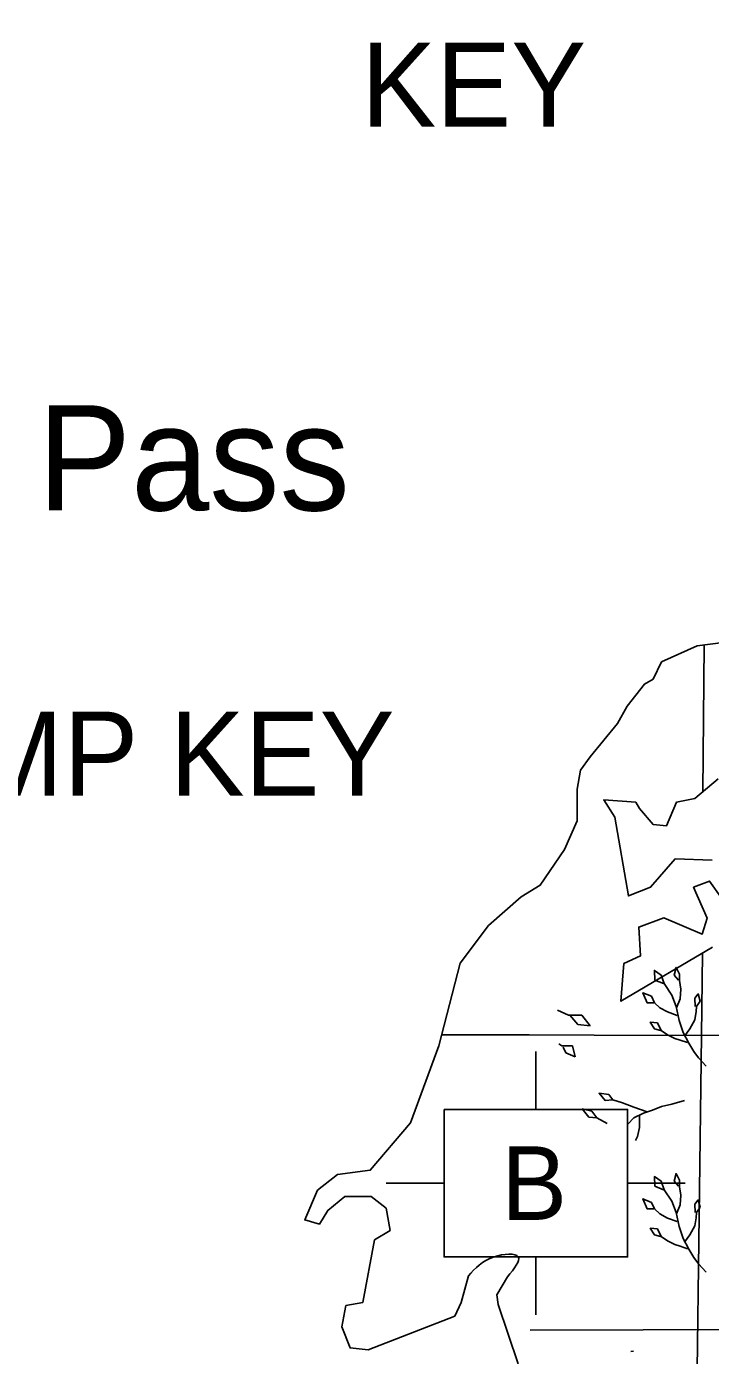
# Model space of a CAD drawing. Extents: x 380424 to 701066, y 1117407 to 1412949.
# Drawn here: x 485366 to 488619, y 1219155 to 1225474 of the extents above; entities that cross this region are included whole.
import ezdxf

# ---------------------------------------------------------------- set-up
doc = ezdxf.new("R2010")
doc.units = 0
for name, color, linetype in [('Bayou and Harbor etc Text', 7, 'Continuous'), ('Cities Incorporated Area', 7, 'Continuous'), ('Culture', 7, 'Continuous'), ('Islands Text Coastal (Keys etc)', 7, 'Continuous'), ('Local Roads Paved', 7, 'Continuous'), ('Mangroves', 7, 'Continuous'), ('Section Lines', 7, 'Continuous')]:
    doc.layers.add(name, color=color, linetype=linetype)

msp = doc.modelspace()

# ---------------------------------------------------------------- linework, layer by layer
at = {"layer": 'Cities Incorporated Area'}
for points in [[(488913.9, 1222575.8), (488557, 1222529), (488387.3, 1222452.9), (488346.3, 1222370.9), (488305.4, 1222347.5), (488223.4, 1222242.1), (488176.6, 1222160.1), (488047.9, 1222002), (488001.1, 1221938.9), (487986, 1221848.3), (487986, 1221697.5), (487925.7, 1221561.7), (487810.1, 1221390.7), (487719.6, 1221335.4), (487563.8, 1221199.6), (487428.1, 1221020), (487327.6, 1220628), (487191.9, 1220261.5), (487000.9, 1220036), (486845.1, 1220015.9), (486749.6, 1219940.4), (486689.3, 1219799.6), (486759.7, 1219779.5), (486799.9, 1219844.9), (486880.3, 1219910.3), (487006, 1219910.3), (487076.3, 1219854.9), (487096.4, 1219749.3), (487021, 1219704.1), (486965.8, 1219407.4), (486885.3, 1219392.3), (486865.2, 1219291.7), (486905.4, 1219191.1), (486990.9, 1219181.1), (487403, 1219342), (487433.2, 1219407.4), (487468.3, 1219533.1)], [(488627.2, 1221510.2), (488451.6, 1221516.1), (488334.6, 1221381.4), (488229.3, 1221340.4), (488164.9, 1221715.1), (488112.3, 1221797.1), (488264.4, 1221785.4), (488282, 1221756.1), (488346.3, 1221680), (488410.7, 1221674.1), (488457.5, 1221785.4), (488545.3, 1221803), (488656.5, 1221896.6)], [(488629.8, 1221096.6), (488193.9, 1220839.1), (488207.1, 1221018.7), (488287.2, 1221054.5), (488278.1, 1221191.8), (488398.1, 1221235.7), (488580.4, 1221158.9), (488603.8, 1221235), (488539.4, 1221381.4), (488615.5, 1221410.7), (488674, 1221328.7)], [(487654.3, 1219528.1), (487604, 1219442.6), (487609.1, 1219397.3), (487704.6, 1219115.7)]]:
    msp.add_lwpolyline(points, dxfattribs=at)
msp.add_spline([(487468.3, 1219533.1), (487591.1, 1219624.2), (487705.5, 1219624.2), (487654.3, 1219528.1)], degree=3, dxfattribs=at)
at = {"layer": 'Culture'}
for p, q in [((487788.5, 1220600.2), (487788.5, 1220325.2)), ((487077, 1219974.6), (487352, 1219974.6)), ((488225, 1219974.6), (488500, 1219974.6)), ((487788.5, 1219623.9), (487788.5, 1219348.9))]:
    msp.add_line(p, q, dxfattribs=at)
msp.add_lwpolyline([(487352, 1220325.2), (488225, 1220325.2), (488225, 1219623.9), (487352, 1219623.9)], close=True, dxfattribs=at)
at = {"layer": 'Local Roads Paved'}
msp.add_lwpolyline([(504046.1, 1219425.2), (495145.7, 1219377.2), (494695.7, 1219372.9), (493679, 1219291.9), (487761.7, 1219275.6)], dxfattribs=at)
at = {"layer": 'Mangroves'}
for points in [[(488598.9, 1220531.1), (488562, 1220570.4), (488540.9, 1220600.5), (488515.9, 1220639.8), (488490.2, 1220691.3), (488470.2, 1220748.5), (488455.9, 1220814.3), (488435.8, 1220868.7), (488398.6, 1220923), (488384.3, 1220963), (488352.9, 1220985.9), (488355.7, 1220940.2), (488395.8, 1220923)], [(488458.7, 1220808.6), (488475.9, 1220851.5), (488478.7, 1220897.3), (488473, 1220937.3), (488473, 1220968.8), (488455.9, 1221000.2), (488447.3, 1220963), (488467.3, 1220940.2)], [(488461.6, 1220771.4), (488415.8, 1220788.6), (488378.6, 1220808.6), (488352.9, 1220831.5), (488338.6, 1220862.9), (488298.5, 1220880.1), (488318.6, 1220831.5), (488350, 1220831.5)], [(488495.7, 1220673.4), (488521.6, 1220708.5), (488544.5, 1220751.4), (488551.2, 1220790.1), (488553.1, 1220814.3), (488570.3, 1220840), (488561.7, 1220874.4), (488544.5, 1220854.4), (488547.4, 1220814.3)], [(487892.6, 1220797.2), (487944.4, 1220773.7)], [(487944.4, 1220773.7), (488008.3, 1220773.7)], [(487989.1, 1220729), (487950.7, 1220773.7)], [(488008.3, 1220773.7), (488046.6, 1220722.6)], [(488046.6, 1220722.6), (487989.1, 1220729)], [(488510.2, 1220642.7), (488475.9, 1220654.1), (488450.1, 1220662.7), (488415.8, 1220679.9), (488384.3, 1220699.9), (488367.2, 1220737.1), (488332.9, 1220739.9), (488352.9, 1220708.5), (488381.5, 1220699.9)], [(487897.8, 1220637.1), (487912.4, 1220626.7)], [(487912.4, 1220626.7), (487963.5, 1220626.7)], [(487931.6, 1220594.8), (487918.8, 1220620.3)], [(487976.3, 1220575.6), (487931.6, 1220594.8)], [(487963.5, 1220626.7), (487976.3, 1220575.6)], [(488318.5, 1220313.1), (488255.6, 1220336), (488201.3, 1220356), (488155.5, 1220370.3), (488118.3, 1220367.4), (488089.7, 1220401.8), (488135.5, 1220396.1), (488155.5, 1220370.3)], [(488055.4, 1220316), (488009.6, 1220327.4)], [(488009.6, 1220327.4), (488041.1, 1220287.4)], [(488344.3, 1220321.7), (488301.4, 1220307.4)], [(488387.2, 1220338.8), (488344.3, 1220321.7)], [(488435.8, 1220350.3), (488387.2, 1220338.8)], [(488495.9, 1220367.4), (488435.8, 1220350.3)], [(488041.1, 1220287.4), (488078.3, 1220284.5)], [(488078.3, 1220284.5), (488055.4, 1220316)], [(488128.2, 1220258.6), (488078.3, 1220284.5)], [(488255.6, 1220284.5), (488226.5, 1220255.4)], [(488301.4, 1220307.4), (488255.6, 1220284.5)], [(488281.4, 1220295.9), (488281.4, 1220238.7)], [(488272.8, 1220195.8), (488263.4, 1220177)], [(488281.4, 1220238.7), (488272.8, 1220195.8)], [(488598.9, 1219551.1), (488562, 1219590.4), (488540.9, 1219620.6), (488515.9, 1219659.8), (488490.2, 1219711.3), (488470.2, 1219768.5), (488455.9, 1219834.3), (488435.8, 1219888.7), (488398.6, 1219943), (488384.3, 1219983), (488352.9, 1220005.9), (488355.7, 1219960.2), (488395.8, 1219943)], [(488458.7, 1219828.6), (488475.9, 1219871.5), (488478.7, 1219917.3), (488473, 1219957.3), (488473, 1219988.8), (488455.9, 1220020.2), (488447.3, 1219983), (488467.3, 1219960.2)], [(488461.6, 1219791.4), (488415.8, 1219808.6), (488378.6, 1219828.6), (488352.9, 1219851.5), (488338.6, 1219882.9), (488298.5, 1219900.1), (488318.6, 1219851.5), (488350, 1219851.5)], [(488495.7, 1219693.4), (488521.6, 1219728.5), (488544.5, 1219771.4), (488551.2, 1219810.1), (488553.1, 1219834.3), (488570.3, 1219860.1), (488561.7, 1219894.4), (488544.5, 1219874.4), (488547.4, 1219834.3)], [(488510.2, 1219662.7), (488475.9, 1219674.1), (488450.1, 1219682.7), (488415.8, 1219699.9), (488384.3, 1219719.9), (488367.2, 1219757.1), (488332.9, 1219759.9), (488352.9, 1219728.5), (488381.5, 1219719.9)], [(488252.8, 1219175.8), (488241.5, 1219173.7)], [(488249.8, 1219172.2), (488249.9, 1219172.9)]]:
    msp.add_lwpolyline(points, dxfattribs=at)
at = {"layer": 'Section Lines'}
msp.add_line((488590.3, 1222533.4), (488583.9, 1221835.5), dxfattribs=at)
for points in [[(488581.8, 1221068.2), (488577.2, 1220675.7), (491241.5, 1220693), (493878.6, 1220719), (493890.6, 1225474.1)], [(488581.8, 1221068.2), (488577.2, 1220675.7), (488066.1, 1220678.6), (487757.5, 1220679.2), (487340.7, 1220679.1)], [(488555, 1218964.1), (488577.2, 1220675.7), (491241.5, 1220693), (493878.6, 1220719), (493868.4, 1217607)], [(487340.7, 1220679.1), (488066.1, 1220678.6), (488577.2, 1220675.7), (488555, 1218964.1)]]:
    msp.add_lwpolyline(points, dxfattribs=at)

# ---------------------------------------------------------------- texts
at = {"layer": 'Bayou and Harbor etc Text'}
msp.add_text('Big Pass', height=500, rotation=0.00032, dxfattribs=at).set_placement((484265.3, 1223173.3))
at = {"layer": 'Culture'}
msp.add_text('B', height=350, dxfattribs=at).set_placement((487624.9, 1219799.6))
at = {"layer": 'Islands Text Coastal (Keys etc)'}
for s, rotation, p in [('KEY', 0.00031, (486958.2, 1224998)), ('CAMP KEY', 0.00033, (484352.7, 1221816.7))]:
    msp.add_text(s, height=400, rotation=rotation, dxfattribs=at).set_placement(p)

doc.saveas('drawing.dxf')
